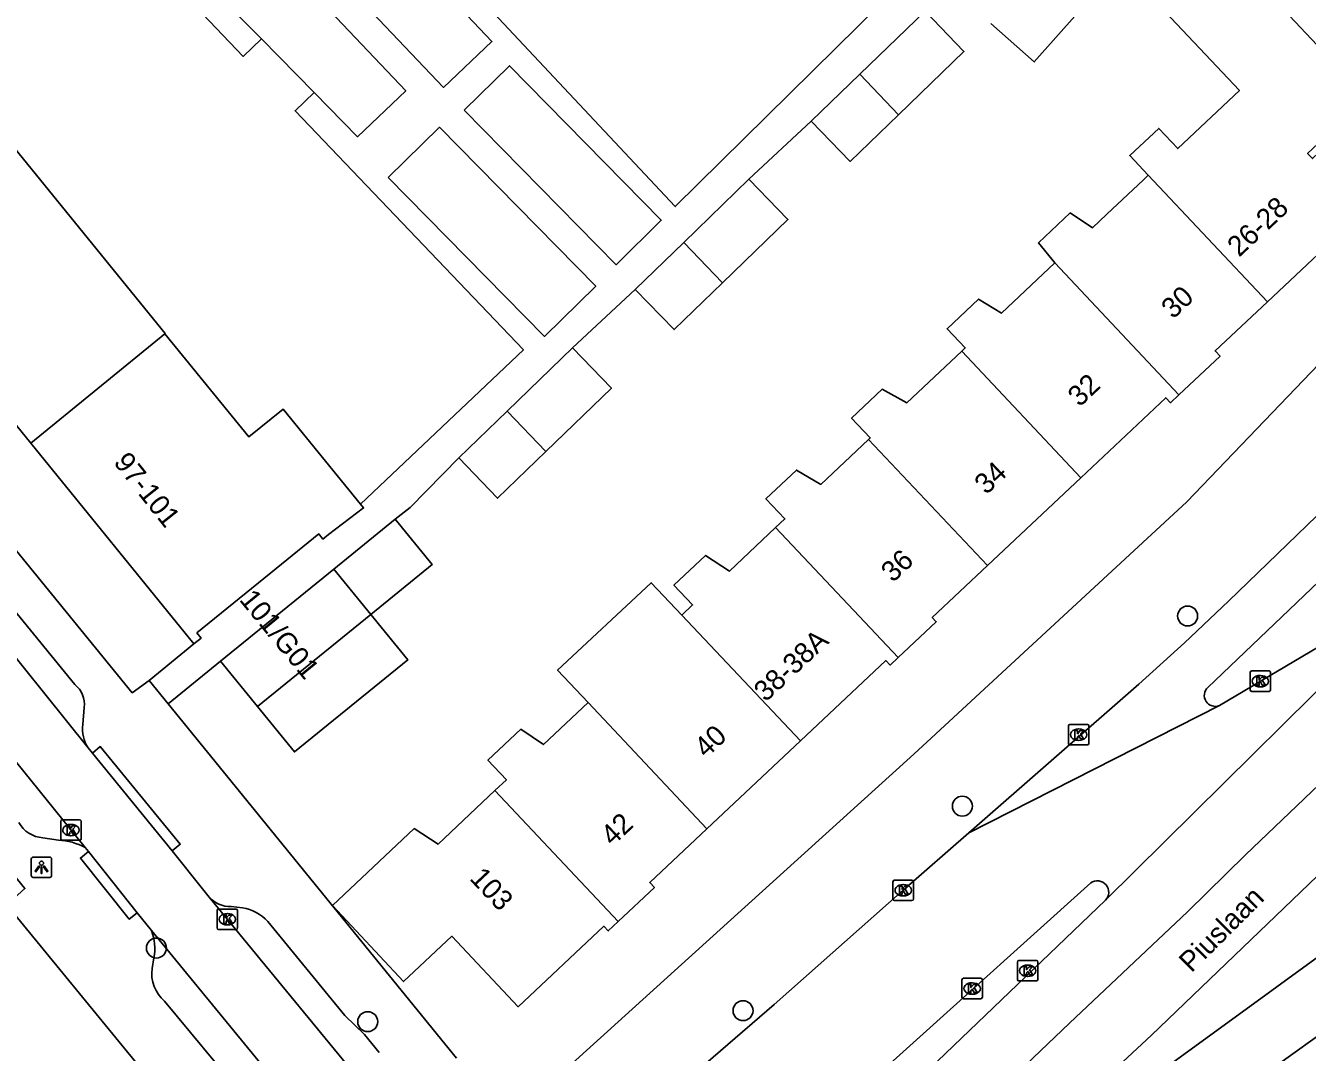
# Model space of a CAD drawing. Extents: x 162074 to 163034, y 381824 to 382557.
# Drawn here: x 162697.9 to 162760.7, y 382017.5 to 382067.8 of the extents above; entities that cross this region are included whole.
import ezdxf

# ---------------------------------------------------------------- set-up
doc = ezdxf.new("R2010")
doc.units = 0
for name, color, linetype in [('IMGEO_Boom', 7, 'Continuous'), ('IMGEO_Fietspad_open', 7, 'Continuous'), ('IMGEO_Kolk', 7, 'Continuous'), ('IMGEO_Lichtpunt', 7, 'Continuous'), ('IMGEO_Openbare_ruimte_label', 7, 'Continuous'), ('IMGEO_Pand', 7, 'Continuous'), ('IMGEO_Pand_nummerreeks', 7, 'Continuous'), ('IMGEO_Rijbaan_lokaal_open', 7, 'Continuous'), ('IMGEO_Rijbaan_regionaal_gesloten', 7, 'Continuous'), ('IMGEO_Voetpad_open', 7, 'Continuous')]:
    doc.layers.add(name, color=color, linetype=linetype)

msp = doc.modelspace()

# ---------------------------------------------------------------- linework, layer by layer
at = {"layer": 'IMGEO_Boom'}
for centre in [(162754.797, 382038.853), (162743.772, 382029.543), (162704.33, 382022.6), (162733.038, 382019.534), (162714.671, 382018.996)]:
    msp.add_circle(centre, 0.489, dxfattribs=at)
at = {"layer": 'IMGEO_Fietspad_open'}
for points in [[(162744.085, 382028.233), (162752.404, 382035.511), (162754.646, 382037.542), (162756.804, 382039.587), (162762.552, 382045.151), (162765.967, 382048.461)], [(162764.128, 382043.311), (162755.789, 382035.359)]]:
    msp.add_lwpolyline(points, dxfattribs=at)
msp.add_arc((162756.147, 382034.962), 0.534, 132.00498, 293.29574, dxfattribs=at)
at = {"layer": 'IMGEO_Kolk'}
for p, q in [((162757.857, 382035.236), (162757.857, 382036.088)), ((162757.932, 382036.162), (162758.784, 382036.162)), ((162758.345, 382035.942), (162758.37, 382035.942)), ((162758.858, 382036.088), (162758.858, 382035.236)), ((162758.368, 382035.382), (162758.343, 382035.382)), ((162758.784, 382035.162), (162757.932, 382035.162)), ((162748.964, 382032.618), (162748.964, 382033.47)), ((162749.039, 382033.544), (162749.891, 382033.544)), ((162749.965, 382033.47), (162749.965, 382032.618)), ((162749.475, 382032.764), (162749.45, 382032.764)), ((162749.452, 382033.324), (162749.477, 382033.324)), ((162749.891, 382032.544), (162749.039, 382032.544)), ((162699.645, 382027.948), (162699.645, 382028.8)), ((162699.72, 382028.874), (162700.572, 382028.874)), ((162700.133, 382028.654), (162700.158, 382028.654)), ((162700.646, 382028.8), (162700.646, 382027.948)), ((162700.572, 382027.874), (162699.72, 382027.874)), ((162700.156, 382028.094), (162700.131, 382028.094)), ((162740.453, 382025.929), (162741.305, 382025.929)), ((162740.378, 382025.003), (162740.378, 382025.855)), ((162740.866, 382025.709), (162740.891, 382025.709)), ((162741.379, 382025.855), (162741.379, 382025.003)), ((162741.305, 382024.929), (162740.453, 382024.929)), ((162740.889, 382025.149), (162740.864, 382025.149)), ((162707.301, 382023.583), (162707.301, 382024.435)), ((162707.376, 382024.509), (162708.228, 382024.509)), ((162707.789, 382024.289), (162707.814, 382024.289)), ((162708.302, 382024.435), (162708.302, 382023.583)), ((162708.228, 382023.509), (162707.376, 382023.509)), ((162707.812, 382023.729), (162707.787, 382023.729)), ((162746.469, 382021.062), (162746.469, 382021.914)), ((162746.544, 382021.988), (162747.396, 382021.988)), ((162746.957, 382021.768), (162746.982, 382021.768)), ((162747.47, 382021.914), (162747.47, 382021.062)), ((162743.751, 382020.193), (162743.751, 382021.045)), ((162743.826, 382021.119), (162744.678, 382021.119)), ((162744.239, 382020.899), (162744.264, 382020.899)), ((162744.752, 382021.045), (162744.752, 382020.193)), ((162747.396, 382020.988), (162746.544, 382020.988)), ((162746.98, 382021.208), (162746.955, 382021.208)), ((162744.262, 382020.339), (162744.237, 382020.339)), ((162744.678, 382020.119), (162743.826, 382020.119))]:
    msp.add_line(p, q, dxfattribs=at)
for points in [[(162757.857, 382035.236), (162757.857, 382036.088)], [(162757.932, 382036.162), (162758.784, 382036.162)], [(162758.858, 382036.088), (162758.858, 382035.236)], [(162758.178, 382035.862), (162758.301, 382035.862), (162758.301, 382035.711), (162758.431, 382035.862), (162758.595, 382035.862), (162758.449, 382035.711), (162758.602, 382035.462), (162758.45, 382035.462), (162758.365, 382035.626), (162758.301, 382035.559), (162758.301, 382035.462), (162758.178, 382035.462), (162758.178, 382035.862)], [(162758.784, 382035.162), (162757.932, 382035.162)], [(162748.964, 382032.618), (162748.964, 382033.47)], [(162749.039, 382033.544), (162749.891, 382033.544)], [(162749.965, 382033.47), (162749.965, 382032.618)], [(162749.285, 382033.244), (162749.408, 382033.244), (162749.408, 382033.093), (162749.538, 382033.244), (162749.702, 382033.244), (162749.556, 382033.093), (162749.709, 382032.844), (162749.557, 382032.844), (162749.472, 382033.008), (162749.408, 382032.941), (162749.408, 382032.844), (162749.285, 382032.844), (162749.285, 382033.244)], [(162749.891, 382032.544), (162749.039, 382032.544)], [(162699.645, 382027.948), (162699.645, 382028.8)], [(162699.72, 382028.874), (162700.572, 382028.874)], [(162699.966, 382028.574), (162700.089, 382028.574), (162700.089, 382028.423), (162700.219, 382028.574), (162700.383, 382028.574), (162700.237, 382028.423), (162700.39, 382028.174), (162700.238, 382028.174), (162700.153, 382028.338), (162700.089, 382028.271), (162700.089, 382028.174), (162699.966, 382028.174), (162699.966, 382028.574)], [(162700.646, 382028.8), (162700.646, 382027.948)], [(162700.572, 382027.874), (162699.72, 382027.874)], [(162740.453, 382025.929), (162741.305, 382025.929)], [(162740.378, 382025.003), (162740.378, 382025.855)], [(162740.699, 382025.629), (162740.822, 382025.629), (162740.822, 382025.478), (162740.952, 382025.629), (162741.116, 382025.629), (162740.97, 382025.478), (162741.123, 382025.229), (162740.971, 382025.229), (162740.886, 382025.393), (162740.822, 382025.326), (162740.822, 382025.229), (162740.699, 382025.229), (162740.699, 382025.629)], [(162741.379, 382025.855), (162741.379, 382025.003)], [(162741.305, 382024.929), (162740.453, 382024.929)], [(162707.301, 382023.583), (162707.301, 382024.435)], [(162707.376, 382024.509), (162708.228, 382024.509)], [(162707.622, 382024.209), (162707.745, 382024.209), (162707.745, 382024.058), (162707.875, 382024.209), (162708.039, 382024.209), (162707.893, 382024.058), (162708.046, 382023.809), (162707.894, 382023.809), (162707.809, 382023.973), (162707.745, 382023.906), (162707.745, 382023.809), (162707.622, 382023.809), (162707.622, 382024.209)], [(162708.302, 382024.435), (162708.302, 382023.583)], [(162708.228, 382023.509), (162707.376, 382023.509)], [(162746.469, 382021.062), (162746.469, 382021.914)], [(162746.544, 382021.988), (162747.396, 382021.988)], [(162746.79, 382021.688), (162746.913, 382021.688), (162746.913, 382021.537), (162747.043, 382021.688), (162747.207, 382021.688), (162747.061, 382021.537), (162747.214, 382021.288), (162747.062, 382021.288), (162746.977, 382021.452), (162746.913, 382021.385), (162746.913, 382021.288), (162746.79, 382021.288), (162746.79, 382021.688)], [(162747.47, 382021.914), (162747.47, 382021.062)], [(162743.751, 382020.193), (162743.751, 382021.045)], [(162743.826, 382021.119), (162744.678, 382021.119)], [(162744.752, 382021.045), (162744.752, 382020.193)], [(162747.396, 382020.988), (162746.544, 382020.988)], [(162744.072, 382020.819), (162744.195, 382020.819), (162744.195, 382020.668), (162744.325, 382020.819), (162744.489, 382020.819), (162744.343, 382020.668), (162744.496, 382020.419), (162744.344, 382020.419), (162744.259, 382020.583), (162744.195, 382020.516), (162744.195, 382020.419), (162744.072, 382020.419), (162744.072, 382020.819)], [(162744.678, 382020.119), (162743.826, 382020.119)]]:
    msp.add_lwpolyline(points, dxfattribs=at)
for centre, start, end in [((162757.934, 382036.086), 91.55205, 178.44795), ((162757.934, 382036.086), 91.55205, 178.44795), ((162758.782, 382036.086), 1.55205, 88.44795), ((162758.782, 382036.086), 1.55205, 88.44795), ((162757.934, 382035.238), 181.55205, 268.44795), ((162757.934, 382035.238), 181.55205, 268.44795), ((162758.782, 382035.238), 271.55205, 358.44795), ((162758.782, 382035.238), 271.55205, 358.44795), ((162749.041, 382033.468), 91.55205, 178.44795), ((162749.041, 382033.468), 91.55205, 178.44795), ((162749.889, 382033.468), 1.55205, 88.44795), ((162749.889, 382033.468), 1.55205, 88.44795), ((162749.041, 382032.62), 181.55205, 268.44795), ((162749.041, 382032.62), 181.55205, 268.44795), ((162749.889, 382032.62), 271.55205, 358.44795), ((162749.889, 382032.62), 271.55205, 358.44795), ((162699.722, 382028.798), 91.55205, 178.44795), ((162699.722, 382028.798), 91.55205, 178.44795), ((162700.57, 382028.798), 1.55205, 88.44795), ((162700.57, 382028.798), 1.55205, 88.44795), ((162699.722, 382027.95), 181.55205, 268.44795), ((162699.722, 382027.95), 181.55205, 268.44795), ((162700.57, 382027.95), 271.55205, 358.44795), ((162700.57, 382027.95), 271.55205, 358.44795), ((162740.455, 382025.853), 91.55205, 178.44795), ((162740.455, 382025.853), 91.55205, 178.44795), ((162741.303, 382025.853), 1.55205, 88.44795), ((162741.303, 382025.853), 1.55205, 88.44795), ((162740.455, 382025.005), 181.55205, 268.44795), ((162740.455, 382025.005), 181.55205, 268.44795), ((162741.303, 382025.005), 271.55205, 358.44795), ((162741.303, 382025.005), 271.55205, 358.44795), ((162707.378, 382024.433), 91.55205, 178.44795), ((162707.378, 382024.433), 91.55205, 178.44795), ((162708.226, 382024.433), 1.55205, 88.44795), ((162708.226, 382024.433), 1.55205, 88.44795), ((162707.378, 382023.585), 181.55205, 268.44795), ((162707.378, 382023.585), 181.55205, 268.44795), ((162708.226, 382023.585), 271.55205, 358.44795), ((162708.226, 382023.585), 271.55205, 358.44795), ((162746.546, 382021.912), 91.55205, 178.44795), ((162746.546, 382021.912), 91.55205, 178.44795), ((162747.394, 382021.912), 1.55205, 88.44795), ((162747.394, 382021.912), 1.55205, 88.44795), ((162743.828, 382021.043), 91.55205, 178.44795), ((162743.828, 382021.043), 91.55205, 178.44795), ((162744.676, 382021.043), 1.55205, 88.44795), ((162744.676, 382021.043), 1.55205, 88.44795), ((162746.546, 382021.064), 181.55205, 268.44795), ((162746.546, 382021.064), 181.55205, 268.44795), ((162747.394, 382021.064), 271.55205, 358.44795), ((162747.394, 382021.064), 271.55205, 358.44795), ((162743.828, 382020.195), 181.55205, 268.44795), ((162743.828, 382020.195), 181.55205, 268.44795), ((162744.676, 382020.195), 271.55205, 358.44795), ((162744.676, 382020.195), 271.55205, 358.44795)]:
    msp.add_arc(centre, 0.0765, start, end, dxfattribs=at)
for centre, major_axis, ratio, start_param, end_param in [((162758.344, 382035.662), (-0.387, 0.002), 0.722429, 4.712389, 7.853982), ((162758.369, 382035.662), (-0.39, 0.002), 0.717154, 1.570796, 4.712389), ((162749.451, 382033.044), (-0.387, 0.002), 0.722429, 4.712389, 7.853982), ((162749.476, 382033.044), (-0.39, 0.002), 0.717154, 1.570796, 4.712389), ((162700.132, 382028.374), (-0.387, 0.002), 0.722429, 4.712389, 7.853982), ((162700.157, 382028.374), (-0.39, 0.002), 0.717154, 1.570796, 4.712389), ((162740.865, 382025.429), (-0.387, 0.002), 0.722429, 4.712389, 7.853982), ((162740.89, 382025.429), (-0.39, 0.002), 0.717154, 1.570796, 4.712389), ((162707.788, 382024.009), (-0.387, 0.002), 0.722429, 4.712389, 7.853982), ((162707.813, 382024.009), (-0.39, 0.002), 0.717154, 1.570796, 4.712389), ((162746.956, 382021.488), (-0.387, 0.002), 0.722429, 4.712389, 7.853982), ((162746.981, 382021.488), (-0.39, 0.002), 0.717154, 1.570796, 4.712389), ((162744.238, 382020.619), (-0.387, 0.002), 0.722429, 4.712389, 7.853982), ((162744.263, 382020.619), (-0.39, 0.002), 0.717154, 1.570796, 4.712389)]:
    msp.add_ellipse(centre, major_axis=major_axis, ratio=ratio, start_param=start_param, end_param=end_param, dxfattribs=at)
at = {"layer": 'IMGEO_Lichtpunt'}
for p, q in [((162698.206, 382026.956), (162698.206, 382026.149)), ((162698.206, 382026.956), (162698.206, 382026.149)), ((162699.108, 382027.051), (162698.3, 382027.051)), ((162699.108, 382027.051), (162698.3, 382027.051)), ((162699.202, 382026.149), (162699.202, 382026.956)), ((162699.202, 382026.149), (162699.202, 382026.956)), ((162698.3, 382026.055), (162699.108, 382026.055)), ((162698.3, 382026.055), (162699.108, 382026.055))]:
    msp.add_line(p, q, dxfattribs=at)
for points in [[(162698.58, 382026.62), (162698.619, 382026.592), (162698.431, 382026.33), (162698.393, 382026.357), (162698.58, 382026.62)], [(162698.682, 382026.572), (162698.729, 382026.572), (162698.729, 382026.25), (162698.682, 382026.25), (162698.682, 382026.572)], [(162698.792, 382026.592), (162698.83, 382026.619), (162699.017, 382026.357), (162698.978, 382026.329), (162698.792, 382026.592)]]:
    msp.add_lwpolyline(points, dxfattribs=at)
msp.add_circle((162698.705, 382026.754), 0.0994, dxfattribs=at)
for centre, start, end in [((162698.3, 382026.956), 90, 180), ((162698.3, 382026.956), 90, 180), ((162699.108, 382026.956), 0, 90), ((162699.108, 382026.956), 0, 90), ((162698.3, 382026.149), 180, 270), ((162698.3, 382026.149), 180, 270), ((162699.108, 382026.149), 270, 0), ((162699.108, 382026.149), 270, 360)]:
    msp.add_arc(centre, 0.0946, start, end, dxfattribs=at)
at = {"layer": 'IMGEO_Pand'}
for points in [[(162711.109, 382072.387), (162713.487, 382074.642), (162720.751, 382066.981), (162718.373, 382064.725), (162711.109, 382072.387)], [(162749.792, 382073.063), (162751.412, 382071.628), (162751.908, 382071.189), (162751.526, 382070.758), (162747.29, 382065.974), (162745.174, 382067.848)], [(162712.042, 382064.473), (162714.165, 382062.309), (162716.535, 382064.555), (162709.127, 382072.369), (162706.623, 382069.995), (162709.467, 382067.097)], [(162752.868, 382060.426), (162751.964, 382061.386), (162753.385, 382062.722), (162754.313, 382061.735), (162757.336, 382064.577), (162752.874, 382069.324), (162756.005, 382072.267), (162763.573, 382064.216), (162760.672, 382061.489), (162760.905, 382061.242), (162761.532, 382061.832), (162763.464, 382059.778), (162762.847, 382059.198), (162763.381, 382058.631), (162758.701, 382054.231)], [(162738.751, 382065.372), (162741.945, 382068.461)], [(162741.945, 382068.461), (162743.85, 382066.491), (162740.644, 382063.391)], [(162709.467, 382067.097), (162712.042, 382064.473)], [(162719.39, 382063.61), (162721.602, 382065.786), (162729.04, 382058.224), (162726.828, 382056.048), (162719.39, 382063.61)], [(162736.375, 382063.074), (162738.751, 382065.372)], [(162738.751, 382065.372), (162740.644, 382063.391)], [(162740.644, 382063.391), (162738.279, 382061.105), (162736.375, 382063.074)], [(162696.756, 382062.525), (162704.754, 382052.68), (162704.742, 382052.67)], [(162715.679, 382060.318), (162723.33, 382052.54), (162725.832, 382055.001), (162718.182, 382062.779), (162715.679, 382060.318)], [(162748.291, 382056.132), (162747.499, 382057.119), (162749.056, 382058.583), (162750.134, 382057.856), (162750.844, 382058.524), (162752.637, 382060.209), (162752.868, 382060.426)], [(162752.868, 382060.426), (162758.701, 382054.231)], [(162730.136, 382057.14), (162733.33, 382060.229)], [(162733.33, 382060.229), (162735.235, 382058.259), (162732.029, 382055.159)], [(162698.176, 382047.321), (162690.177, 382057.165)], [(162727.76, 382054.842), (162730.136, 382057.14)], [(162730.136, 382057.14), (162732.029, 382055.159)], [(162743.74, 382051.811), (162743.914, 382051.974), (162743.029, 382052.915), (162744.57, 382054.365), (162745.685, 382053.681), (162748.291, 382056.132)], [(162748.291, 382056.132), (162754.366, 382049.68)], [(162732.029, 382055.159), (162729.664, 382052.873), (162727.76, 382054.842)], [(162758.701, 382054.231), (162756.144, 382051.827), (162756.382, 382051.575), (162754.366, 382049.68)], [(162704.742, 382052.67), (162698.176, 382047.321)], [(162704.742, 382052.67), (162708.856, 382047.62), (162710.528, 382048.982), (162714.323, 382044.324)], [(162721.499, 382048.887), (162724.693, 382051.976)], [(162724.693, 382051.976), (162726.598, 382050.006), (162723.392, 382046.906)], [(162739.186, 382047.495), (162739.264, 382047.569), (162738.35, 382048.541), (162739.853, 382049.955), (162741.05, 382049.28), (162743.74, 382051.811)], [(162743.74, 382051.811), (162749.568, 382045.622)], [(162754.366, 382049.68), (162753.955, 382049.294), (162753.729, 382049.534), (162749.568, 382045.622)], [(162719.123, 382046.589), (162721.499, 382048.887)], [(162723.392, 382046.906), (162721.499, 382048.887)], [(162698.176, 382047.321), (162706.166, 382037.487)], [(162734.631, 382043.179), (162735.086, 382043.607), (162734.159, 382044.593), (162735.654, 382045.998), (162736.848, 382045.297), (162739.186, 382047.495)], [(162739.186, 382047.495), (162744.997, 382041.323)], [(162723.392, 382046.906), (162721.027, 382044.62), (162719.123, 382046.589)], [(162749.568, 382045.622), (162744.997, 382041.323)], [(162714.323, 382044.324), (162714.469, 382044.144), (162712.753, 382042.836), (162712.481, 382042.616), (162712.277, 382042.867), (162710.195, 382041.175), (162706.314, 382038.022), (162706.517, 382037.772), (162706.166, 382037.487)], [(162713.018, 382041.148), (162716.021, 382043.588)], [(162716.021, 382043.588), (162717.824, 382041.369), (162714.821, 382038.929)], [(162730.042, 382038.899), (162730.566, 382039.392), (162729.658, 382040.358), (162731.207, 382041.815), (162732.369, 382041.052), (162734.631, 382043.179)], [(162734.631, 382043.179), (162740.624, 382036.814)], [(162707.472, 382036.641), (162713.018, 382041.148)], [(162714.821, 382038.929), (162713.018, 382041.148)], [(162744.997, 382041.323), (162742.297, 382038.784), (162742.494, 382038.573), (162740.624, 382036.814)], [(162725.457, 382034.616), (162723.965, 382036.195), (162728.55, 382040.478), (162730.042, 382038.899)], [(162714.821, 382038.929), (162716.627, 382036.706), (162711.081, 382032.2), (162709.276, 382034.42)], [(162709.276, 382034.42), (162714.821, 382038.929)], [(162735.844, 382032.737), (162730.042, 382038.899)], [(162709.276, 382034.42), (162707.472, 382036.641)], [(162740.624, 382036.814), (162740.235, 382036.449), (162740.027, 382036.671), (162735.844, 382032.737)], [(162720.896, 382030.305), (162721.458, 382030.833), (162720.557, 382031.792), (162722.168, 382033.307), (162723.271, 382032.56), (162725.457, 382034.616)], [(162731.273, 382028.439), (162725.457, 382034.616)], [(162735.844, 382032.737), (162731.273, 382028.439)], [(162726.93, 382023.897), (162726.441, 382023.437), (162726.225, 382023.667), (162722.033, 382019.725), (162718.788, 382023.177), (162716.424, 382020.954), (162712.945, 382024.683), (162716.951, 382028.451), (162718.115, 382027.69), (162720.896, 382030.305)], [(162726.93, 382023.897), (162720.896, 382030.305)], [(162731.273, 382028.439), (162728.47, 382025.804), (162728.699, 382025.561), (162726.93, 382023.897)]]:
    msp.add_lwpolyline(points, dxfattribs=at)
at = {"layer": 'IMGEO_Rijbaan_lokaal_open'}
for points in [[(162632.463, 382107.512), (162633.363, 382106.764), (162637.528, 382103.355), (162640.492, 382100.753), (162643.616, 382097.962), (162645.88, 382095.919), (162649.953, 382092.047), (162656.352, 382085.883), (162661.786, 382080.023), (162665.941, 382075.363), (162670.915, 382069.283), (162677.257, 382061.594), (162690.501, 382045.455), (162700.991, 382032.398)], [(162700.837, 382027.518), (162688.141, 382043.258), (162674.967, 382059.407), (162668.985, 382066.736), (162663.312, 382073.605), (162659.777, 382077.535), (162656.64, 382080.856), (162652.505, 382085.285), (162648.402, 382089.208), (162644.268, 382093.096), (162641.364, 382095.768), (162638.389, 382098.519), (162635.285, 382101.121), (162630.556, 382105.1)], [(162756.358, 382034.471), (162765.677, 382039.991), (162766.691, 382040.677)], [(162756.358, 382034.471), (162744.085, 382028.233)], [(162700.991, 382032.398), (162701.197, 382032.142)], [(162701.197, 382032.142), (162705.106, 382027.366)], [(162726.574, 382012.905), (162726.69, 382013.012), (162729.315, 382015.305), (162734.558, 382019.836), (162740.88, 382025.429), (162744.085, 382028.233)], [(162700.999, 382027.318), (162700.837, 382027.518)], [(162703.393, 382024.323), (162700.999, 382027.318)], [(162705.106, 382027.366), (162706.642, 382025.417), (162706.905, 382025.098)], [(162750.053, 382025.788), (162732.012, 382009.534), (162731.798, 382009.34)], [(162706.905, 382025.098), (162715.769, 382014.327)], [(162704.082, 382023.46), (162703.393, 382024.323)], [(162713.195, 382012.363), (162704.082, 382023.46)]]:
    msp.add_lwpolyline(points, dxfattribs=at)
msp.add_arc((162750.375, 382025.327), 0.562, 315.99598, 124.8735, dxfattribs=at)
at = {"layer": 'IMGEO_Rijbaan_regionaal_gesloten'}
for points in [[(162766.691, 382040.677), (162750.779, 382024.936)], [(162769.492, 382038.496), (162763.389, 382032.664), (162757.636, 382027.166), (162754.789, 382024.377), (162749.013, 382018.928), (162743.336, 382013.499), (162737.438, 382008.003), (162731.726, 382002.679), (162728.73, 382000.13), (162726.543, 381998.269), (162720.477, 381993.259), (162714.322, 381988.176), (162711.181, 381985.616), (162709.59, 381984.248), (162678.587, 381958.753)], [(162726.692, 381994.177), (162731.928, 381998.712), (162753.027, 382018.342), (162770.462, 382035.069), (162772.059, 382036.498)], [(162775.869, 382032.852), (162753.538, 382016.6)], [(162727.302, 381993.446), (162734.416, 381998.779), (162737.897, 382001.398), (162744.462, 382006.076), (162750.794, 382010.733), (162757.246, 382015.477), (162763.753, 382020.148), (162769.758, 382024.585), (162776.979, 382029.804)], [(162732.963, 382007.864), (162733.142, 382008.036), (162750.779, 382024.936)]]:
    msp.add_lwpolyline(points, dxfattribs=at)
at = {"layer": 'IMGEO_Voetpad_open'}
for points in [[(162703.978, 382035.693), (162703.148, 382035.093), (162670.958, 382074.601), (162661.799, 382085.06), (162655.945, 382091.08), (162647.911, 382098.48), (162636.114, 382108.989), (162636.712, 382109.62)], [(162635.74, 382107.124), (162640.854, 382102.64), (162644.714, 382099.239), (162647.612, 382096.578), (162649.653, 382094.474), (162652.644, 382091.575), (162656.8, 382087.366), (162659.676, 382084.366), (162663.274, 382080.489), (162666.276, 382077.044), (162668.961, 382073.917), (162672.089, 382070.116), (162681.677, 382058.36), (162700.333, 382035.494)], [(162740.929, 382069.968), (162729.718, 382058.893), (162710.696, 382079.187), (162696.169, 382094.204), (162703.821, 382102.808)], [(162709.893, 382008.991), (162697.016, 382024.713), (162697.896, 382025.512), (162662.101, 382069.449), (162657.097, 382075.079), (162644.151, 382088.188), (162639.153, 382092.704), (162629.902, 382100.628)], [(162705.107, 382072.229), (162703.935, 382071.111), (162708.576, 382066.246), (162709.467, 382067.097)], [(162712.042, 382064.473), (162711.114, 382063.587), (162722.289, 382051.875), (162714.323, 382044.324)], [(162736.375, 382063.074), (162733.33, 382060.229)], [(162724.511, 382016.802), (162741.397, 382032.094), (162754.763, 382044.439), (162765.79, 382055.945)], [(162727.76, 382054.842), (162724.693, 382051.976)], [(162719.123, 382046.589), (162716.74, 382044.172), (162716.021, 382043.588)], [(162706.166, 382037.487), (162703.978, 382035.693)], [(162707.472, 382036.641), (162704.906, 382034.553)], [(162703.978, 382035.693), (162704.906, 382034.553)], [(162700.8, 382034.376), (162700.723, 382033.539)], [(162704.906, 382034.553), (162719.013, 382017.214)], [(162701.197, 382032.142), (162701.583, 382032.459), (162705.492, 382027.683), (162705.106, 382027.366)], [(162699.531, 382027.88), (162698.769, 382027.996)], [(162703.393, 382024.323), (162703.003, 382024.011), (162700.609, 382027.006), (162700.999, 382027.318)], [(162707.98, 382024.629), (162708.538, 382024.565)], [(162709.781, 382023.902), (162713.543, 382019.301), (162714.516, 382018.364), (162715.224, 382017.493)], [(162704.114, 382021.602), (162704.204, 382022.122)], [(162711.875, 382012.981), (162710.884, 382013.099), (162710.261, 382013.427), (162709.572, 382014.104), (162708.457, 382015.49), (162704.733, 382020.002)]]:
    msp.add_lwpolyline(points, dxfattribs=at)
for centre, radius, start, end in [((162699.582, 382034.524), 1.227, 353.08156, 52.26002), ((162702.403, 382033.332), 1.693, 172.96428, 213.47197), ((162698.868, 382029.452), 1.459, 208.89039, 266.11693), ((162699.407, 382024.896), 2.987, 61.39421, 87.62093), ((162707.963, 382026.056), 1.427, 222.16614, 270.69259), ((162708.219, 382022.471), 2.118, 42.50038, 81.34986), ((162701.861, 382022.583), 2.388, 348.87399, 21.54576), ((162705.879, 382021.365), 1.781, 172.36018, 229.94023)]:
    msp.add_arc(centre, radius, start, end, dxfattribs=at)

# ---------------------------------------------------------------- texts
at = {"layer": 'IMGEO_Openbare_ruimte_label'}
msp.add_text('Piuslaan', height=1, rotation=45.04049, dxfattribs=at).set_placement((162754.984, 382021.356))
at = {"layer": 'IMGEO_Pand_nummerreeks'}
for s, rotation, p in [('26-28', 43.2354, (162757.317, 382056.388)), ('30', 43.24112, (162754.089, 382053.353)), ('32', 43.23841, (162749.513, 382049.051)), ('97-101', 308.39942, (162702.194, 382046.365)), ('34', 43.23841, (162744.944, 382044.754)), ('36', 43.23841, (162740.372, 382040.455)), ('101/G01', 309.36932, (162708.351, 382039.637)), ('38-38A', 43.12767, (162734.147, 382034.611)), ('40', 43.23841, (162731.231, 382031.86)), ('42', 43.23841, (162726.655, 382027.557)), ('103', 313.23518, (162719.617, 382025.973))]:
    msp.add_text(s, height=1, rotation=rotation, dxfattribs=at).set_placement(p)

doc.saveas('drawing.dxf')
